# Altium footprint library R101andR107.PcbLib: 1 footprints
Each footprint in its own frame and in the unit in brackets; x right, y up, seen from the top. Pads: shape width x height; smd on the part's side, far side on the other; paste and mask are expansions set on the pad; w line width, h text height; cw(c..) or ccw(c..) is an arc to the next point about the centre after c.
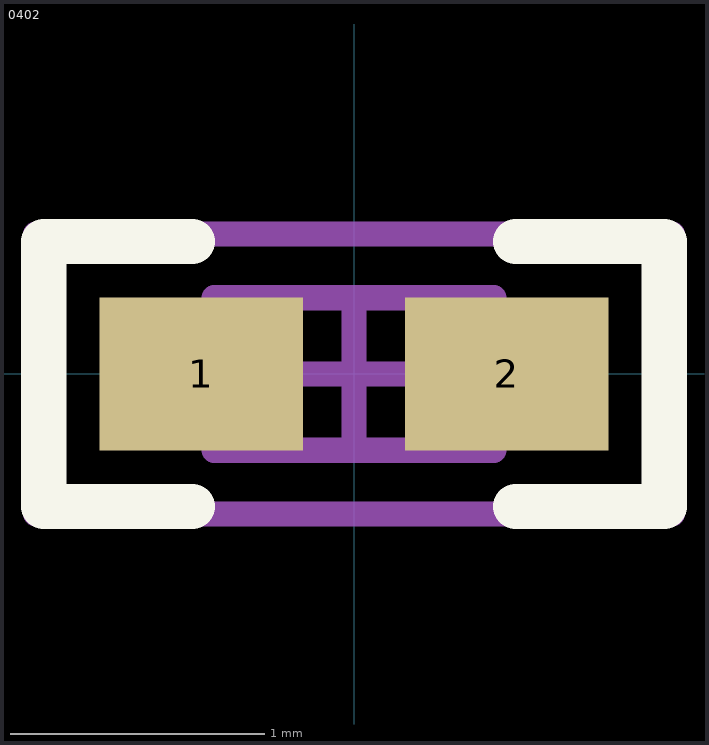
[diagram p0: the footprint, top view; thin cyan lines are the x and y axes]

## 0402 [mm] "0402 from SM-752 data"
height 0.6
pads (2):
  rect 0.8x0.6 smd: 1(-0.6,0) 2(0.6,0)
Top Overlay:
  lines w0.178: -0.635,-0.521 -1.219,-0.521 -1.219,0.521 -0.635,0.521 ; 0.635,-0.521 1.219,-0.521 1.219,0.521 0.635,0.521
Mechanical 5:
  lines w0.1: -1.25,-0.55 1.25,-0.55 1.25,0.55 -1.25,0.55 -1.25,-0.55
  text ".Designator" at 1.016,0.254 h0.61
Mechanical 13:
  lines w0.1: -0.35,-0.3 -0.35,0.3 ; 0.35,-0.3 0.35,0.3 ; -0.55,-0.3 -0.55,0.3 0.55,0.3 0.55,-0.3 -0.55,-0.3
Mechanical 15:
  lines w0.1: -0.3,0 0.3,0 ; 0,-0.3 0,0.3 ; -1.25,-0.55 -1.25,0.55 1.25,0.55 1.25,-0.55 -1.25,-0.55
3D body: height 0.6, standoff 0, extent -0.549,-0.299 -0.351,0.299
3D body: height 0.6, standoff 0, extent -0.349,-0.299 0.349,0.299
3D body: height 0.6, standoff 0, extent 0.351,-0.299 0.549,0.299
